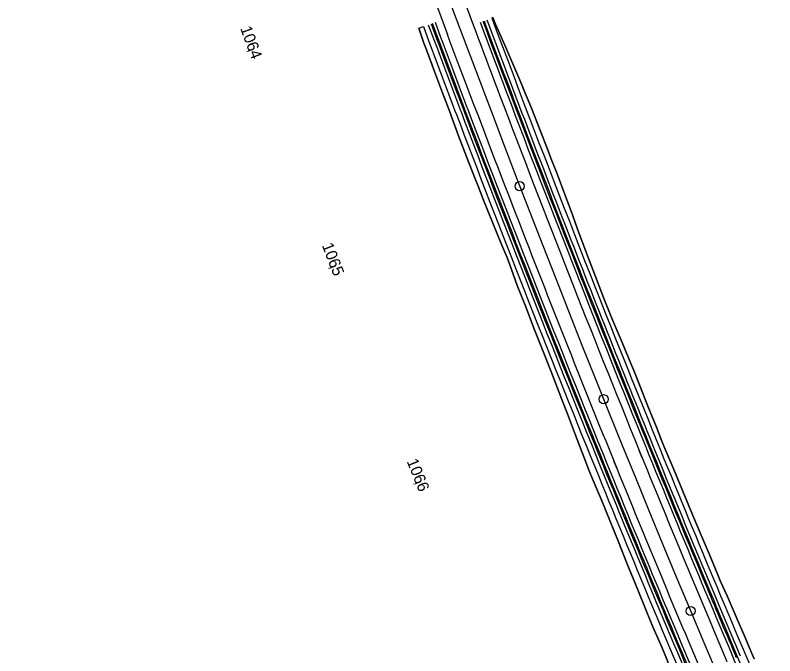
# Model space of a CAD drawing. Extents: x -678487 to -674601, y -1104811 to -1093295.
# Drawn here: x -675631.4 to -675299.5, y -1103207.5 to -1102927.7 of the extents above; entities that cross this region are included whole.
import ezdxf

# ---------------------------------------------------------------- set-up
doc = ezdxf.new("R2010")
doc.units = 0
for name, color, linetype in [('SOxxxxxx_Osa_bod_P', 7, 'Continuous'), ('SOxxxxxx_Staničení_Popis', 7, 'Continuous'), ('SOxxxxxx_ŽSp_hrana', 7, 'Continuous'), ('SOxxxxxx_ŽSp_násyp_plocha', 7, 'Continuous'), ('SOxxxxxx_ŽSp_odvodnění', 7, 'Continuous'), ('SOxxxxxx_ŽSp_zářez_hrana', 7, 'Continuous'), ('SOxxxxxx_ŽSp_zářez_plocha', 7, 'Continuous')]:
    doc.layers.add(name, color=color, linetype=linetype)

msp = doc.modelspace()

# ---------------------------------------------------------------- linework, layer by layer
at = {"layer": 'SOxxxxxx_Osa_bod_P'}
msp.add_arc((-668878.21, -1100481.61), 7002.25, 195.326264, 203.497517, dxfattribs=at)
at = {"layer": 'SOxxxxxx_Staničení_Popis'}
for p, q in [((-675410.99, -1103002.39), (-675410.99, -1103002.39)), ((-675374.33, -1103095.43), (-675374.33, -1103095.43)), ((-675336.34, -1103187.93), (-675336.34, -1103187.93))]:
    msp.add_line(p, q, dxfattribs=at)
for centre in [(-675410.99, -1103002.39), (-675374.33, -1103095.43), (-675336.34, -1103187.93)]:
    msp.add_circle(centre, 2, dxfattribs=at)
at = {"layer": 'SOxxxxxx_ŽSp_hrana'}
for p, q in [((-675357.5, -1103120.97), (-675358.79, -1103117.8)), ((-675368.64, -1103125.5), (-675369.93, -1103122.33))]:
    msp.add_line(p, q, dxfattribs=at)
msp.add_lwpolyline([(-675430.85, -1102967.3), (-675430.9, -1102967.16), (-675434.45, -1102957.8), (-675437.98, -1102948.44), (-675441.49, -1102939.07), (-675442.6, -1102936.12)], dxfattribs=at)
for radius, start, end in [(6996.24, 199.956641, 200.501391), (7008.26, 199.956641, 200.501391), (6996.24, 200.501391, 200.772602), (6996.24, 200.772602, 202.135642), (7008.26, 200.773766, 201.318516), (7008.26, 201.318516, 202.135642), (6996.24, 202.163624, 202.952767), (7008.26, 202.163624, 202.952767)]:
    msp.add_arc((-668878.21, -1100481.61), radius, start, end, dxfattribs=at)
at = {"layer": 'SOxxxxxx_ŽSp_násyp_plocha'}
for p, q in [((-675358.79, -1103117.8), (-675357.5, -1103120.97)), ((-675369.93, -1103122.33), (-675368.64, -1103125.5))]:
    msp.add_line(p, q, dxfattribs=at)
at = {"layer": 'SOxxxxxx_ŽSp_odvodnění'}
for p, q in [((-675427.12, -1102930.33), (-675426.02, -1102933.27)), ((-675449.73, -1102931.45), (-675447.33, -1102937.89)), ((-675449.21, -1102931.26), (-675446.81, -1102937.69)), ((-675447.33, -1102937.89), (-675446.22, -1102940.84)), ((-675446.22, -1102940.84), (-675442.7, -1102950.21)), ((-675442.7, -1102950.21), (-675439.17, -1102959.59)), ((-675439.17, -1102959.59), (-675435.63, -1102968.95)), ((-675435.63, -1102968.95), (-675435.58, -1102969.09)), ((-675435.11, -1102968.76), (-675435.06, -1102968.89)), ((-675354.62, -1103116.11), (-675353.34, -1103119.27)), ((-675354.11, -1103115.9), (-675352.83, -1103119.06)), ((-675374.6, -1103124.23), (-675373.31, -1103127.41)), ((-675374.09, -1103124.03), (-675372.8, -1103127.2))]:
    msp.add_line(p, q, dxfattribs=at)
for radius, start, end in [(6991.19, 200.501391, 200.772602), (6991.74, 200.527128, 202.135642), (7012.76, 200.501391, 200.772602), (6991.19, 200.772602, 202.135642), (7013.31, 200.773766, 202.135642), (7012.76, 200.773766, 202.135642), (6991.74, 202.163624, 202.680392), (6991.19, 202.163624, 203.225142), (7013.31, 202.163624, 203.225142), (7012.76, 202.163624, 203.225142), (6991.74, 202.680392, 202.952767)]:
    msp.add_arc((-668878.21, -1100481.61), radius, start, end, dxfattribs=at)
at = {"layer": 'SOxxxxxx_ŽSp_zářez_hrana'}
for p, q in [((-675423.24, -1102928.88), (-675422.14, -1102931.82)), ((-675422.73, -1102928.69), (-675421.52, -1102931.59)), ((-675455.03, -1102933.43), (-675452.83, -1102939.95)), ((-675453.1, -1102932.71), (-675450.7, -1102939.15)), ((-675450.93, -1102931.9), (-675448.53, -1102938.33)), ((-675448.01, -1102930.82), (-675445.61, -1102937.25)), ((-675421.52, -1102931.59), (-675417.56, -1102940.76)), ((-675445.61, -1102937.25), (-675444.51, -1102940.2)), ((-675452.83, -1102939.95), (-675451.76, -1102942.91)), ((-675448.53, -1102938.33), (-675447.42, -1102941.29)), ((-675444.51, -1102940.2), (-675440.99, -1102949.57)), ((-675451.76, -1102942.91), (-675448.28, -1102952.31)), ((-675447.42, -1102941.29), (-675443.9, -1102950.66)), ((-675417.56, -1102940.76), (-675413.63, -1102949.94)), ((-675440.99, -1102949.57), (-675437.46, -1102958.94)), ((-675413.63, -1102949.94), (-675409.66, -1102959.1)), ((-675448.28, -1102952.31), (-675444.69, -1102961.67)), ((-675443.9, -1102950.66), (-675440.37, -1102960.04)), ((-675440.37, -1102960.04), (-675436.82, -1102969.41)), ((-675437.46, -1102958.94), (-675433.92, -1102968.3)), ((-675409.66, -1102959.1), (-675409.6, -1102959.23)), ((-675409.6, -1102959.23), (-675405.82, -1102968.32)), ((-675444.69, -1102961.67), (-675441.17, -1102971.06)), ((-675438.99, -1102970.23), (-675438.94, -1102970.36)), ((-675436.82, -1102969.41), (-675436.77, -1102969.54)), ((-675433.92, -1102968.3), (-675433.86, -1102968.44)), ((-675405.82, -1102968.32), (-675402.14, -1102977.59)), ((-675441.17, -1102971.06), (-675441.12, -1102971.19)), ((-675441.12, -1102971.19), (-675437.69, -1102980.46)), ((-675437.69, -1102980.46), (-675434.07, -1102989.81)), ((-675402.14, -1102977.59), (-675398.57, -1102986.91)), ((-675398.57, -1102986.91), (-675397.35, -1102990.1)), ((-675434.07, -1102989.81), (-675430.46, -1102999.16)), ((-675397.35, -1102990.1), (-675395, -1102996.22)), ((-675395, -1102996.22), (-675391.45, -1103005.54)), ((-675430.46, -1102999.16), (-675429.22, -1103002.36)), ((-675429.22, -1103002.36), (-675426.78, -1103008.48)), ((-675391.45, -1103005.54), (-675387.99, -1103014.9)), ((-675426.78, -1103008.48), (-675422.98, -1103017.76)), ((-675387.99, -1103014.9), (-675385.74, -1103021.21)), ((-675422.98, -1103017.76), (-675419.3, -1103027.08)), ((-675385.74, -1103021.21), (-675384.54, -1103024.26)), ((-675384.54, -1103024.26), (-675381.04, -1103033.61)), ((-675419.3, -1103027.08), (-675416.69, -1103033.29)), ((-675416.69, -1103033.29), (-675415.45, -1103036.34)), ((-675415.45, -1103036.34), (-675412.07, -1103045.78)), ((-675381.04, -1103033.61), (-675377.49, -1103042.93)), ((-675377.49, -1103042.93), (-675373.9, -1103052.24)), ((-675412.07, -1103045.78), (-675408.34, -1103055.09)), ((-675373.9, -1103052.24), (-675370.16, -1103061.49)), ((-675408.34, -1103055.09), (-675404.79, -1103064.46)), ((-675370.16, -1103061.49), (-675366.3, -1103070.69)), ((-675404.79, -1103064.46), (-675401.11, -1103073.79)), ((-675366.3, -1103070.69), (-675362.43, -1103079.88)), ((-675401.11, -1103073.79), (-675397.34, -1103083.07)), ((-675362.43, -1103079.88), (-675361.19, -1103082.93)), ((-675397.34, -1103083.07), (-675393.76, -1103092.44)), ((-675361.19, -1103082.93), (-675358.7, -1103089.14)), ((-675358.7, -1103089.14), (-675354.99, -1103098.4)), ((-675393.76, -1103092.44), (-675392.58, -1103095.52)), ((-675392.58, -1103095.52), (-675390.18, -1103101.8)), ((-675354.99, -1103098.4), (-675351.26, -1103107.65)), ((-675390.18, -1103101.8), (-675386.66, -1103111.19)), ((-675351.26, -1103107.65), (-675348.84, -1103113.75)), ((-675386.66, -1103111.19), (-675383.03, -1103120.54)), ((-675352.93, -1103115.42), (-675351.64, -1103118.58)), ((-675350.78, -1103114.54), (-675349.49, -1103117.7)), ((-675348.84, -1103113.75), (-675347.54, -1103116.91)), ((-675355.81, -1103116.59), (-675354.52, -1103119.75)), ((-675347.54, -1103116.91), (-675343.71, -1103126.12)), ((-675383.03, -1103120.54), (-675380.6, -1103126.67)), ((-675377.94, -1103125.59), (-675376.65, -1103128.76)), ((-675375.79, -1103124.72), (-675374.5, -1103127.89)), ((-675372.91, -1103123.54), (-675371.62, -1103126.72)), ((-675343.71, -1103126.12), (-675339.86, -1103135.32)), ((-675380.6, -1103126.67), (-675379.34, -1103129.86)), ((-675379.34, -1103129.86), (-675375.43, -1103139.09)), ((-675339.86, -1103135.32), (-675336.08, -1103144.41)), ((-675375.43, -1103139.09), (-675371.62, -1103148.36)), ((-675336.08, -1103144.41), (-675332.18, -1103153.73)), ((-675371.62, -1103148.36), (-675367.87, -1103157.66)), ((-675332.18, -1103153.73), (-675328.24, -1103162.9)), ((-675367.87, -1103157.66), (-675364.15, -1103166.97)), ((-675328.24, -1103162.9), (-675324.41, -1103172.11)), ((-675364.15, -1103166.97), (-675360.38, -1103176.26)), ((-675324.41, -1103172.11), (-675323.22, -1103175.03)), ((-675360.38, -1103176.26), (-675356.58, -1103185.54)), ((-675323.22, -1103175.03), (-675320.42, -1103181.26)), ((-675320.42, -1103181.26), (-675316.47, -1103190.42)), ((-675356.58, -1103185.54), (-675355.4, -1103188.47)), ((-675355.4, -1103188.47), (-675352.81, -1103194.83)), ((-675316.47, -1103190.42), (-675312.46, -1103199.55)), ((-675352.81, -1103194.83), (-675348.81, -1103204.03)), ((-675312.46, -1103199.55), (-675309.96, -1103205.47)), ((-675348.81, -1103204.03), (-675345.02, -1103213.31)), ((-675309.96, -1103205.47), (-675308.58, -1103208.74))]:
    msp.add_line(p, q, dxfattribs=at)
for radius, start, end in [(6989.91, 200.501391, 201.263551), (6993.02, 200.501391, 200.772602), (6987.59, 200.527128, 202.135642), (7016.91, 200.501391, 200.772602), (6993.02, 200.772602, 202.135642), (7016.91, 200.773766, 202.135642), (7014.59, 200.773766, 202.135642), (7011.48, 200.773766, 202.135642), (6989.91, 201.263551, 202.135642), (6993.02, 202.163624, 203.225142), (6989.91, 202.163624, 202.952767), (6987.59, 202.163624, 203.225142), (7016.91, 202.163624, 203.225142), (7014.59, 202.163624, 202.952767), (7011.48, 202.163624, 203.225142)]:
    msp.add_arc((-668878.21, -1100481.61), radius, start, end, dxfattribs=at)
at = {"layer": 'SOxxxxxx_ŽSp_zářez_plocha'}
for p, q in [((-675422.73, -1102928.69), (-675423.24, -1102928.88)), ((-675423.24, -1102928.88), (-675422.14, -1102931.82)), ((-675455.03, -1102933.43), (-675453.1, -1102932.71)), ((-675453.1, -1102932.71), (-675450.7, -1102939.15)), ((-675438.99, -1102970.23), (-675438.94, -1102970.36)), ((-675350.78, -1103114.54), (-675349.49, -1103117.7)), ((-675377.94, -1103125.59), (-675376.65, -1103128.76))]:
    msp.add_line(p, q, dxfattribs=at)
for points in [[(-675308.58, -1103208.74), (-675309.96, -1103205.47), (-675312.46, -1103199.55), (-675316.47, -1103190.42), (-675320.42, -1103181.26), (-675323.22, -1103175.03), (-675324.41, -1103172.11), (-675328.24, -1103162.9), (-675332.18, -1103153.73), (-675336.08, -1103144.41), (-675339.86, -1103135.32), (-675343.71, -1103126.12), (-675347.54, -1103116.91), (-675348.84, -1103113.75), (-675351.26, -1103107.65), (-675354.99, -1103098.4), (-675358.7, -1103089.14), (-675361.19, -1103082.93), (-675362.43, -1103079.88), (-675366.3, -1103070.69), (-675370.16, -1103061.49), (-675373.9, -1103052.24), (-675377.49, -1103042.93), (-675381.04, -1103033.61), (-675384.54, -1103024.26), (-675385.74, -1103021.21), (-675387.99, -1103014.9), (-675391.45, -1103005.54), (-675395, -1102996.22), (-675397.35, -1102990.1), (-675398.57, -1102986.91), (-675402.14, -1102977.59), (-675405.82, -1102968.32), (-675409.6, -1102959.23), (-675409.66, -1102959.1), (-675413.63, -1102949.94), (-675417.56, -1102940.76), (-675421.52, -1102931.59), (-675422.73, -1102928.69)], [(-675345.02, -1103213.31), (-675348.81, -1103204.03), (-675352.81, -1103194.83), (-675355.4, -1103188.47), (-675356.58, -1103185.54), (-675360.38, -1103176.26), (-675364.15, -1103166.97), (-675367.87, -1103157.66), (-675371.62, -1103148.36), (-675375.43, -1103139.09), (-675379.34, -1103129.86), (-675380.6, -1103126.67), (-675383.03, -1103120.54), (-675386.66, -1103111.19), (-675390.18, -1103101.8), (-675392.58, -1103095.52), (-675393.76, -1103092.44), (-675397.34, -1103083.07), (-675401.11, -1103073.79), (-675404.79, -1103064.46), (-675408.34, -1103055.09), (-675412.07, -1103045.78), (-675415.45, -1103036.34), (-675416.69, -1103033.29), (-675419.3, -1103027.08), (-675422.98, -1103017.76), (-675426.78, -1103008.48), (-675429.22, -1103002.36), (-675430.46, -1102999.16), (-675434.07, -1102989.81), (-675437.69, -1102980.46), (-675441.12, -1102971.19), (-675441.17, -1102971.06), (-675444.69, -1102961.67), (-675448.28, -1102952.31), (-675451.76, -1102942.91), (-675452.83, -1102939.95), (-675455.03, -1102933.43)]]:
    msp.add_lwpolyline(points, dxfattribs=at)
for radius, start, end in [(6987.59, 200.527128, 202.135642), (7016.91, 200.501391, 200.772602), (7016.91, 200.773766, 202.135642), (6987.59, 202.163624, 203.225142), (7016.91, 202.163624, 203.225142)]:
    msp.add_arc((-668878.21, -1100481.61), radius, start, end, dxfattribs=at)

# ---------------------------------------------------------------- texts
at = {"layer": 'SOxxxxxx_Staničení_Popis'}
for s, rotation, p in [('106', 290.2817, (-675533.18, -1102933.45)), (',', 290.2817, (-675529.87, -1102942.41)), ('4', 290.2817, (-675529.32, -1102943.91)), ('106', 291.0999, (-675497.5, -1103028.21)), (',', 291.0999, (-675494.06, -1103037.13)), ('5', 291.0999, (-675493.48, -1103038.62)), ('106', 291.9181, (-675460.45, -1103122.5)), (',', 291.9181, (-675456.88, -1103131.36)), ('6', 291.9181, (-675456.28, -1103132.84))]:
    msp.add_text(s, height=5, rotation=rotation, dxfattribs=at).set_placement(p)

doc.saveas('drawing.dxf')
